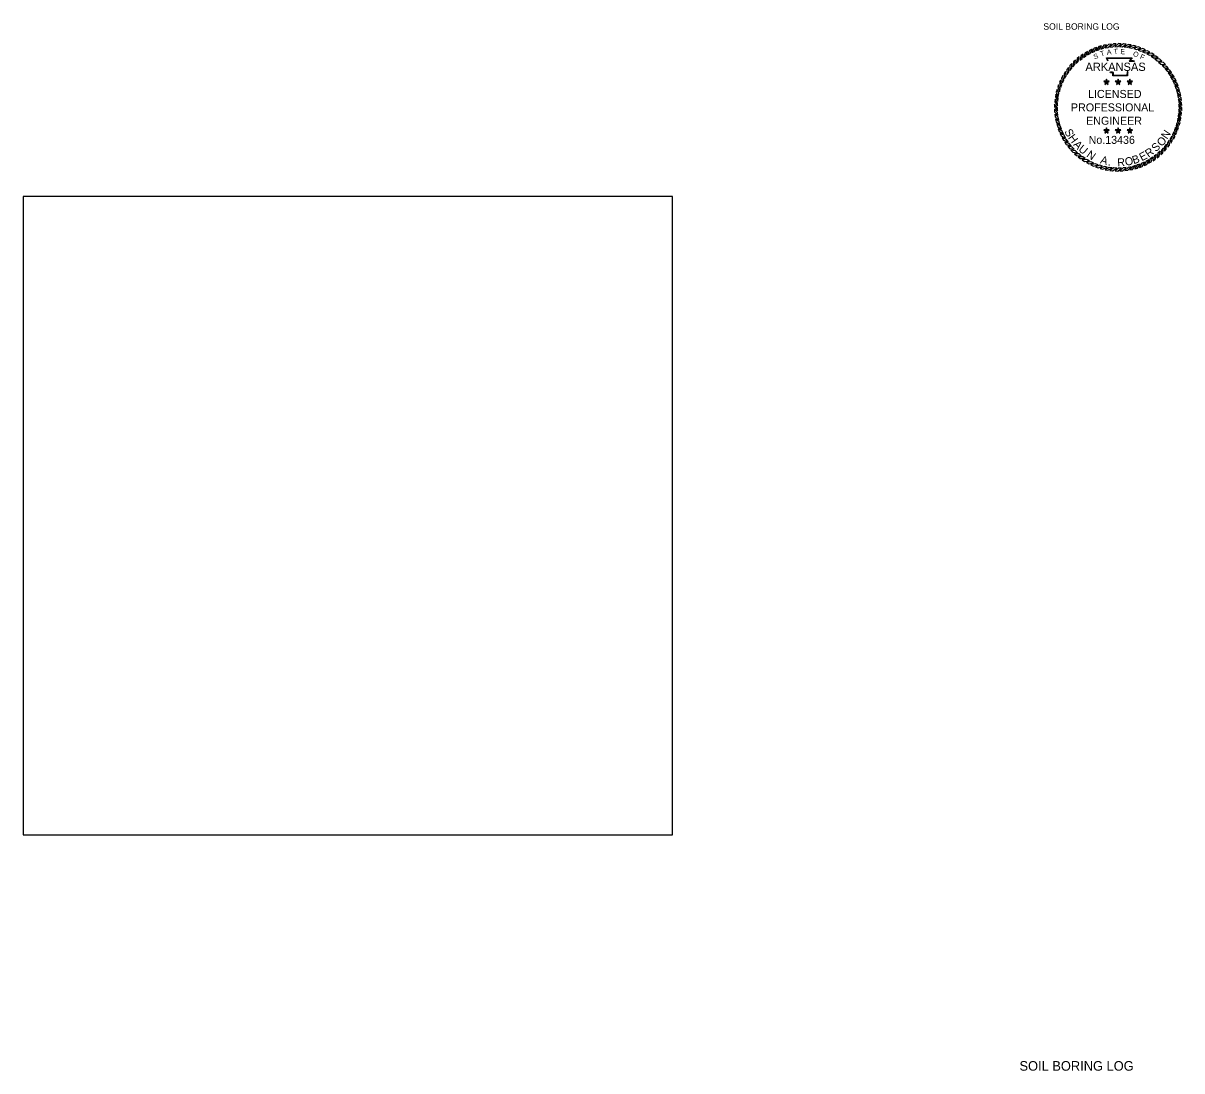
# Model space of a CAD drawing. Extents: x 987302 to 990904, y 1868293 to 1870149.
import ezdxf

# ---------------------------------------------------------------- set-up
doc = ezdxf.new("R2010")
doc.units = 0
for name, color, linetype in [('1', 7, 'Continuous'), ('60', 7, 'Continuous'), ('Default', 7, 'Continuous'), ('G-ANNO-SYMB', 7, 'Continuous')]:
    doc.layers.add(name, color=color, linetype=linetype)

msp = doc.modelspace()

# ---------------------------------------------------------------- linework, layer by layer
at = {"layer": 'Default'}
msp.add_lwpolyline([(989819.1, 1868860.3), (990427.2, 1868860.3), (990427.2, 1869458.4), (989819.1, 1869458.4)], close=True, dxfattribs=at)
at = {"layer": 'G-ANNO-SYMB'}
for points in [[(990838.5, 1869601.1), (990835.9, 1869600.8), (990832.8, 1869597.4), (990835.5, 1869598)], [(990843.1, 1869601.4), (990840.6, 1869601.3), (990837.2, 1869598.2), (990840, 1869598.5)], [(990847.8, 1869601.4), (990845.3, 1869601.5), (990841.7, 1869598.6), (990844.4, 1869598.7)], [(990852.5, 1869601), (990849.9, 1869601.2), (990846.1, 1869598.7), (990848.9, 1869598.6)], [(990812.2, 1869591.7), (990810.1, 1869590.3), (990808.8, 1869585.9), (990811, 1869587.6)], [(990816.2, 1869594.2), (990814, 1869592.9), (990812.4, 1869588.6), (990814.7, 1869590.1)], [(990820.4, 1869596.2), (990818.1, 1869595.1), (990816.2, 1869591), (990818.6, 1869592.3)], [(990824.8, 1869598), (990822.4, 1869597.1), (990820.1, 1869593.1), (990822.7, 1869594.2)], [(990829.3, 1869599.4), (990826.8, 1869598.7), (990824.2, 1869594.9), (990826.8, 1869595.8)], [(990833.8, 1869600.4), (990831.3, 1869599.9), (990828.5, 1869596.3), (990831.1, 1869597.1)], [(990857.1, 1869600.2), (990854.6, 1869600.7), (990850.6, 1869598.4), (990853.3, 1869598.1)], [(990861.6, 1869599), (990859.2, 1869599.7), (990855, 1869597.8), (990857.7, 1869597.2)], [(990866.1, 1869597.5), (990863.7, 1869598.4), (990859.4, 1869596.8), (990862, 1869596.1)], [(990870.4, 1869595.7), (990868.1, 1869596.8), (990863.6, 1869595.5), (990866.2, 1869594.5)], [(990874.5, 1869593.5), (990872.3, 1869594.8), (990867.8, 1869593.9), (990870.3, 1869592.7)], [(990878.5, 1869591), (990876.4, 1869592.4), (990871.8, 1869591.9), (990874.2, 1869590.6)], [(990798.4, 1869579.2), (990796.8, 1869577.2), (990797, 1869572.6), (990798.5, 1869574.9)], [(990801.5, 1869582.8), (990799.7, 1869580.9), (990799.5, 1869576.3), (990801.3, 1869578.4)], [(990804.8, 1869586), (990802.9, 1869584.3), (990802.4, 1869579.7), (990804.3, 1869581.8)], [(990808.4, 1869589), (990806.4, 1869587.4), (990805.5, 1869582.9), (990807.5, 1869584.8)], [(990882.3, 1869588.2), (990880.2, 1869589.8), (990875.7, 1869589.7), (990878, 1869588.1)], [(990885.8, 1869585.2), (990883.9, 1869586.9), (990879.3, 1869587.1), (990881.5, 1869585.4)], [(990889.1, 1869581.8), (990887.3, 1869583.7), (990882.8, 1869584.2), (990884.8, 1869582.3)], [(990892.1, 1869578.2), (990890.5, 1869580.2), (990886, 1869581.1), (990887.9, 1869579.1)], [(990793.1, 1869571.5), (990791.9, 1869569.2), (990792.7, 1869564.8), (990793.9, 1869567.3)], [(990795.6, 1869575.5), (990794.2, 1869573.3), (990794.7, 1869568.8), (990796.1, 1869571.2)], [(990833.9, 1869565.5), (990834.5, 1869566.4), (990833.9, 1869568.3), (990833.3, 1869566.4)], [(990844.8, 1869565.5), (990845.5, 1869566.4), (990844.8, 1869568.3), (990844.2, 1869566.4)], [(990855.7, 1869565.5), (990856.4, 1869566.4), (990855.7, 1869568.3), (990855.1, 1869566.4)], [(990894.8, 1869574.4), (990893.3, 1869576.5), (990889, 1869577.8), (990890.7, 1869575.6)], [(990897.2, 1869570.4), (990895.9, 1869572.6), (990891.6, 1869574.2), (990893.2, 1869571.9)], [(990899.3, 1869566.2), (990898.2, 1869568.5), (990894, 1869570.4), (990895.4, 1869568)], [(990787.6, 1869558.6), (990786.9, 1869556.1), (990788.8, 1869552), (990789.4, 1869554.7)], [(990789.1, 1869563), (990788.2, 1869560.6), (990789.8, 1869556.3), (990790.6, 1869559)], [(990790.9, 1869567.3), (990789.9, 1869565), (990791.1, 1869560.6), (990792.1, 1869563.2)], [(990833.9, 1869565.5), (990833.3, 1869566.4), (990831.3, 1869566.4), (990832.9, 1869565.2)], [(990833.9, 1869565.5), (990832.9, 1869565.2), (990832.3, 1869563.3), (990833.9, 1869564.5)], [(990833.9, 1869565.5), (990834.9, 1869565.2), (990836.5, 1869566.4), (990834.5, 1869566.4)], [(990833.9, 1869565.5), (990833.9, 1869564.5), (990835.5, 1869563.3), (990834.9, 1869565.2)], [(990844.8, 1869565.5), (990844.2, 1869566.4), (990842.2, 1869566.4), (990843.8, 1869565.2)], [(990844.8, 1869565.5), (990843.8, 1869565.2), (990843.2, 1869563.3), (990844.8, 1869564.5)], [(990844.8, 1869565.5), (990845.8, 1869565.2), (990847.4, 1869566.4), (990845.5, 1869566.4)], [(990844.8, 1869565.5), (990844.8, 1869564.5), (990846.4, 1869563.3), (990845.8, 1869565.2)], [(990855.7, 1869565.5), (990855.1, 1869566.4), (990853.2, 1869566.4), (990854.8, 1869565.2)], [(990855.7, 1869565.5), (990854.8, 1869565.2), (990854.1, 1869563.3), (990855.7, 1869564.5)], [(990855.7, 1869565.5), (990856.7, 1869565.2), (990858.3, 1869566.4), (990856.4, 1869566.4)], [(990855.7, 1869565.5), (990855.7, 1869564.5), (990857.4, 1869563.3), (990856.7, 1869565.2)], [(990901, 1869561.8), (990900.1, 1869564.2), (990896.1, 1869566.5), (990897.3, 1869564)], [(990902.4, 1869557.4), (990901.7, 1869559.8), (990897.9, 1869562.4), (990898.9, 1869559.8)], [(990903.5, 1869552.8), (990902.9, 1869555.3), (990899.4, 1869558.2), (990900.1, 1869555.5)], [(990785.7, 1869549.4), (990785.4, 1869546.9), (990787.9, 1869543.1), (990788.1, 1869545.8)], [(990786.5, 1869554.1), (990786, 1869551.5), (990788.2, 1869547.5), (990788.5, 1869550.3)], [(990904.2, 1869548.2), (990903.8, 1869550.7), (990900.5, 1869553.8), (990901, 1869551.1)], [(990904.5, 1869543.5), (990904.3, 1869546.1), (990901.3, 1869549.4), (990901.6, 1869546.7)], [(990785.3, 1869544.8), (990785.2, 1869542.2), (990788, 1869538.6), (990787.9, 1869541.4)], [(990785.2, 1869540.1), (990785.3, 1869537.5), (990788.4, 1869534.2), (990788.1, 1869536.9)], [(990903.2, 1869529.5), (990903.7, 1869532.1), (990901.5, 1869536), (990901.1, 1869533.3)], [(990904, 1869534.1), (990904.3, 1869536.7), (990901.8, 1869540.5), (990901.6, 1869537.7)], [(990904.4, 1869538.8), (990904.5, 1869541.4), (990901.7, 1869545), (990901.8, 1869542.2)], [(990785.5, 1869535.4), (990785.9, 1869532.9), (990789.2, 1869529.8), (990788.7, 1869532.5)], [(990786.2, 1869530.8), (990786.7, 1869528.3), (990790.3, 1869525.4), (990789.6, 1869528.1)], [(990787.3, 1869526.2), (990788, 1869523.8), (990791.8, 1869521.2), (990790.8, 1869523.8)], [(990900.6, 1869520.5), (990901.5, 1869523), (990899.9, 1869527.3), (990899.1, 1869524.6)], [(990902.1, 1869525), (990902.8, 1869527.5), (990900.9, 1869531.6), (990900.3, 1869528.9)], [(990788.7, 1869521.7), (990789.6, 1869519.3), (990793.5, 1869517.1), (990792.4, 1869519.6)], [(990790.4, 1869517.4), (990791.5, 1869515.1), (990795.6, 1869513.1), (990794.3, 1869515.6)], [(990833.9, 1869519.9), (990833.3, 1869520.7), (990831.3, 1869520.7), (990832.9, 1869519.5)], [(990833.9, 1869519.9), (990832.9, 1869519.5), (990832.3, 1869517.7), (990833.9, 1869518.8)], [(990833.9, 1869519.9), (990834.5, 1869520.7), (990833.9, 1869522.6), (990833.3, 1869520.7)], [(990833.9, 1869519.9), (990834.9, 1869519.5), (990836.5, 1869520.7), (990834.5, 1869520.7)], [(990833.9, 1869519.9), (990833.9, 1869518.8), (990835.5, 1869517.7), (990834.9, 1869519.5)], [(990844.8, 1869519.9), (990844.2, 1869520.7), (990842.2, 1869520.7), (990843.8, 1869519.5)], [(990844.8, 1869519.9), (990843.8, 1869519.5), (990843.2, 1869517.7), (990844.8, 1869518.8)], [(990844.8, 1869519.9), (990845.5, 1869520.7), (990844.8, 1869522.6), (990844.2, 1869520.7)], [(990844.8, 1869519.9), (990845.8, 1869519.5), (990847.4, 1869520.7), (990845.5, 1869520.7)], [(990844.8, 1869519.9), (990844.8, 1869518.8), (990846.4, 1869517.7), (990845.8, 1869519.5)], [(990855.7, 1869519.9), (990855.1, 1869520.7), (990853.2, 1869520.7), (990854.8, 1869519.5)], [(990855.7, 1869519.9), (990854.8, 1869519.5), (990854.1, 1869517.7), (990855.7, 1869518.8)], [(990855.7, 1869519.9), (990856.4, 1869520.7), (990855.7, 1869522.6), (990855.1, 1869520.7)], [(990855.7, 1869519.9), (990856.7, 1869519.5), (990858.3, 1869520.7), (990856.4, 1869520.7)], [(990855.7, 1869519.9), (990855.7, 1869518.8), (990857.4, 1869517.7), (990856.7, 1869519.5)], [(990894.1, 1869508.1), (990895.5, 1869510.3), (990895, 1869514.8), (990893.6, 1869512.4)], [(990896.6, 1869512.1), (990897.8, 1869514.3), (990896.9, 1869518.8), (990895.8, 1869516.3)], [(990898.7, 1869516.2), (990899.8, 1869518.6), (990898.6, 1869523), (990897.6, 1869520.4)], [(990792.5, 1869513.2), (990793.8, 1869511), (990798, 1869509.4), (990796.5, 1869511.7)], [(990794.9, 1869509.2), (990796.3, 1869507.1), (990800.7, 1869505.8), (990799, 1869508)], [(990797.6, 1869505.4), (990799.2, 1869503.4), (990803.7, 1869502.5), (990801.8, 1869504.5)], [(990884.9, 1869497.6), (990886.7, 1869499.3), (990887.3, 1869503.9), (990885.4, 1869501.8)], [(990888.2, 1869500.8), (990889.9, 1869502.7), (990890.1, 1869507.3), (990888.4, 1869505.1)], [(990891.3, 1869504.4), (990892.9, 1869506.4), (990892.7, 1869511), (990891.1, 1869508.7)], [(990800.6, 1869501.8), (990802.4, 1869499.9), (990806.9, 1869499.3), (990804.9, 1869501.2)], [(990803.9, 1869498.4), (990805.8, 1869496.7), (990810.3, 1869496.5), (990808.2, 1869498.2)], [(990807.4, 1869495.3), (990809.4, 1869493.8), (990814, 1869493.9), (990811.7, 1869495.5)], [(990811.2, 1869492.5), (990813.3, 1869491.1), (990817.9, 1869491.7), (990815.5, 1869493)], [(990869.2, 1869487.3), (990871.6, 1869488.4), (990873.5, 1869492.6), (990871.1, 1869491.3)], [(990873.4, 1869489.4), (990875.7, 1869490.7), (990877.3, 1869495), (990874.9, 1869493.5)], [(990877.5, 1869491.8), (990879.6, 1869493.3), (990880.8, 1869497.7), (990878.6, 1869496)], [(990881.3, 1869494.5), (990883.3, 1869496.2), (990884.2, 1869500.6), (990882.1, 1869498.8)], [(990815.1, 1869490.1), (990817.4, 1869488.8), (990821.9, 1869489.7), (990819.4, 1869490.9)], [(990819.3, 1869487.9), (990821.6, 1869486.8), (990826, 1869488.1), (990823.4, 1869489)], [(990823.6, 1869486), (990826, 1869485.2), (990830.3, 1869486.7), (990827.6, 1869487.5)], [(990828, 1869484.5), (990830.5, 1869483.9), (990834.7, 1869485.8), (990832, 1869486.3)], [(990832.6, 1869483.4), (990835.1, 1869482.9), (990839.1, 1869485.2), (990836.3, 1869485.5)], [(990837.2, 1869482.6), (990839.7, 1869482.4), (990843.6, 1869484.9), (990840.8, 1869485)], [(990841.9, 1869482.2), (990844.4, 1869482.1), (990848, 1869484.9), (990845.3, 1869484.9)], [(990846.5, 1869482.2), (990849.1, 1869482.3), (990852.5, 1869485.4), (990849.7, 1869485.1)], [(990851.2, 1869482.5), (990853.8, 1869482.8), (990856.9, 1869486.1), (990854.2, 1869485.6)], [(990855.9, 1869483.2), (990858.4, 1869483.7), (990861.2, 1869487.3), (990858.5, 1869486.5)], [(990860.4, 1869484.2), (990862.9, 1869484.9), (990865.4, 1869488.7), (990862.8, 1869487.8)], [(990864.9, 1869485.6), (990867.3, 1869486.5), (990869.5, 1869490.5), (990867, 1869489.4)]]:
    msp.add_lwpolyline(points, close=True, dxfattribs=at)
for points in [[(990835.3, 1869585.1), (990833.9, 1869588.1), (990858, 1869588.1), (990855.9, 1869585.6), (990857.6, 1869585.6), (990858.9, 1869585.6), (990860.3, 1869585.5)], [(990835.6, 1869585.3), (990834.5, 1869587.7), (990857.2, 1869587.7), (990855.1, 1869585.2), (990857.6, 1869585.2), (990858.9, 1869585.2), (990860.3, 1869585.1)], [(990854.2, 1869575), (990853.8, 1869574.7), (990853.6, 1869574.2), (990853.5, 1869572.9), (990853.5, 1869571.3), (990840, 1869571.3), (990840, 1869573.5), (990840, 1869574), (990839.5, 1869574.2), (990837.6, 1869574.2), (990837.3, 1869574.7)], [(990853.9, 1869575.3), (990853.4, 1869574.9), (990853.2, 1869574.2), (990853.1, 1869572.9), (990853.1, 1869571.6), (990840.4, 1869571.6), (990840.4, 1869573.5), (990840.4, 1869574.3), (990839.6, 1869574.6), (990837.8, 1869574.6), (990837.6, 1869574.9)]]:
    msp.add_lwpolyline(points, dxfattribs=at)

# ---------------------------------------------------------------- texts
at = {"layer": '1'}
msp.add_text('SOIL BORING LOG', height=6, rotation=360, dxfattribs=at).set_placement((990774.8, 1869614.5))
at = {"layer": '60'}
msp.add_text('SOIL BORING LOG', height=9, rotation=360, dxfattribs=at).set_placement((990752.4, 1868639.5))
at = {"layer": 'G-ANNO-SYMB'}
for s, height, rotation, p in [('S', 4.75, 19.7726, (990822.7, 1869586.7)), ('T', 4.75, 16.9015, (990828.8, 1869589.4)), ('A', 4.75, 8.6788, (990834.5, 1869590.9)), ('T', 4.75, 1.4789, (990840.7, 1869591.8)), ('E', 4.75, 356.672, (990846.8, 1869591.7)), ('O', 4.75, 341.2218, (990858.3, 1869590.1)), ('F', 4.75, 335.3628, (990864.7, 1869587.6)), ('ARKANSAS', 7.75, 360, (990814.2, 1869575.9)), ('LICENSED', 7.5, 360, (990816.6, 1869550.6)), ('PROFESSIONAL', 7.5, 360, (990800.6, 1869538)), ('ENGINEER', 7.5, 360, (990814.8, 1869525.5)), ('S', 7.5, 298.1636, (990794.2, 1869519.2)), ('H', 7.5, 305.619, (990797.6, 1869513.3)), ('No.13436', 7.47, 360, (990817.2, 1869507.6)), ('O', 7.5, 44.7757, (990885.4, 1869504.6)), ('N', 7.5, 56.1007, (990890.6, 1869511.4)), ('A', 7.5, 313.4472, (990802.3, 1869506.5)), ('U', 7.5, 320.9026, (990807, 1869501.6)), ('R', 7.5, 35.6597, (990873.3, 1869494.5)), ('S', 7.5, 43.4878, (990880.2, 1869499.6)), ('N', 7.5, 324.9326, (990814.6, 1869496)), ('A', 7.5, 343.0991, (990827.6, 1869489.6)), ('R', 7.5, 3.2287, (990844.2, 1869486.4)), ('O', 7.5, 11.4296, (990851.9, 1869486.9)), ('B', 7.5, 18.885, (990859.4, 1869488.5)), ('E', 7.5, 27.8315, (990867, 1869491.2)), ('.', 7.5, 351.3, (990835, 1869487.4))]:
    msp.add_text(s, height=height, rotation=rotation, dxfattribs=at).set_placement(p)

doc.saveas('drawing.dxf')
